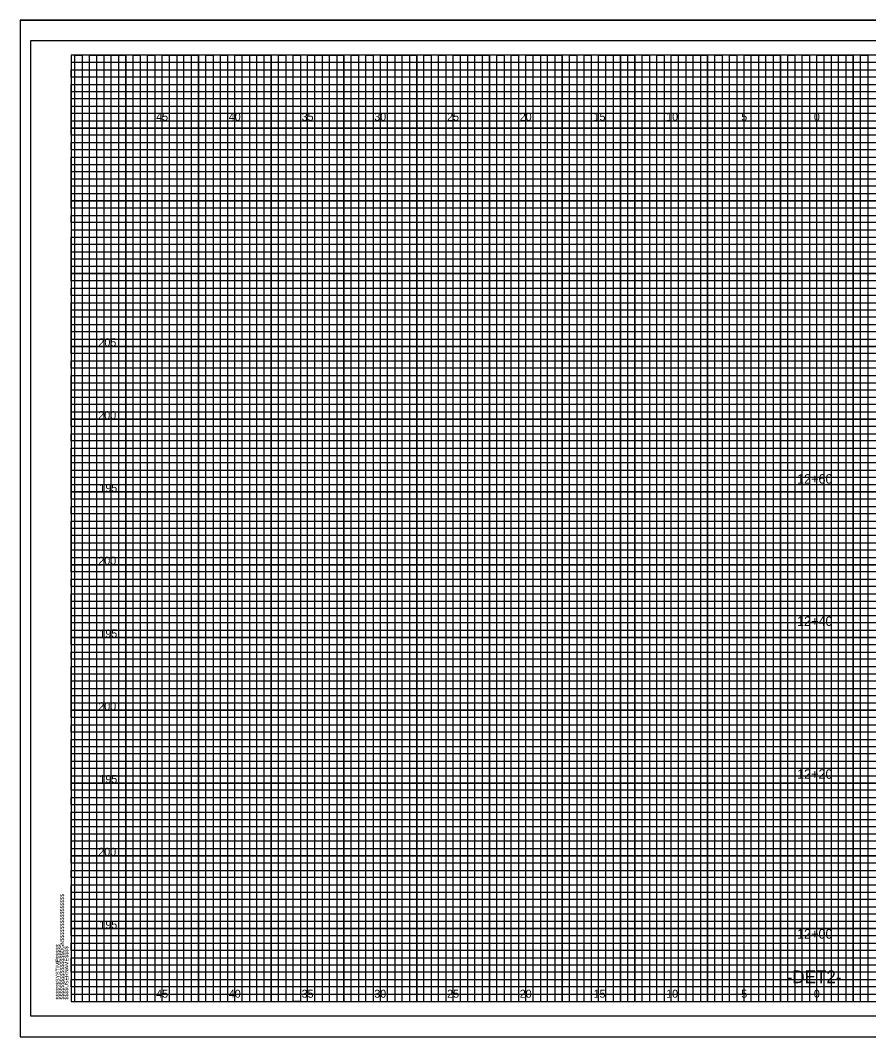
# Model space of a CAD drawing. Extents: x -4 to 103, y -2 to 209.
# Drawn here: x -3.5 to 54.8, y 139.2 to 209.1 of the extents above; entities that cross this region are included whole.
import ezdxf

# ---------------------------------------------------------------- set-up
doc = ezdxf.new("R2010")
doc.units = 0
for name, color, linetype in [('Exist XS Ground Line', 7, 'Continuous'), ('Old_Level_10', 7, 'Continuous'), ('Old_Level_3', 7, 'Continuous'), ('Old_Level_5', 7, 'Continuous'), ('Old_Level_8', 7, 'Continuous'), ('Prop XS Dump Level', 7, 'Continuous'), ('Prop XS Elevation Labels', 7, 'Continuous'), ('Prop XS EOT Tick Mark', 7, 'Continuous'), ('Prop XS Finish Grade', 7, 'Continuous'), ('Prop XS Hydro Elevations', 7, 'Continuous'), ('Prop XS Label Text', 7, 'Continuous')]:
    doc.layers.add(name, color=color, linetype=linetype)

msp = doc.modelspace()

# ---------------------------------------------------------------- linework, layer by layer
at = {"layer": 'Exist XS Ground Line'}
msp.add_lwpolyline([(103, 207.65), (-2.8, 207.65), (-2.8, 140.65), (103, 140.65)], close=True, dxfattribs=at)
at = {"layer": 'Old_Level_10'}
for p, q in [((1.25, 141.65), (1.25, 206.65)), ((3.75, 141.65), (3.75, 206.65)), ((6.25, 141.65), (6.25, 206.65)), ((8.75, 141.65), (8.75, 206.65)), ((11.25, 141.65), (11.25, 206.65)), ((13.75, 141.65), (13.75, 206.65)), ((16.25, 141.65), (16.25, 206.65)), ((18.75, 141.65), (18.75, 206.65)), ((21.25, 141.65), (21.25, 206.65)), ((23.75, 141.65), (23.75, 206.65)), ((26.25, 141.65), (26.25, 206.65)), ((28.75, 141.65), (28.75, 206.65)), ((31.25, 141.65), (31.25, 206.65)), ((33.75, 141.65), (33.75, 206.65)), ((36.25, 141.65), (36.25, 206.65)), ((38.75, 141.65), (38.75, 206.65)), ((41.25, 141.65), (41.25, 206.65)), ((43.75, 141.65), (43.75, 206.65)), ((46.25, 141.65), (46.25, 206.65)), ((48.75, 141.65), (48.75, 206.65)), ((51.25, 141.65), (51.25, 206.65)), ((53.75, 141.65), (53.75, 206.65)), ((0, 204.15), (74.25, 204.15)), ((0, 201.65), (102.5, 201.65)), ((0, 199.15), (102.5, 199.15)), ((0, 196.65), (102.5, 196.65)), ((0, 194.15), (102.5, 194.15)), ((0, 191.65), (102.5, 191.65)), ((0, 189.15), (102.5, 189.15)), ((0, 186.65), (102.5, 186.65)), ((0, 184.15), (102.5, 184.15)), ((0, 181.65), (102.5, 181.65)), ((0, 179.15), (102.5, 179.15)), ((0, 176.65), (102.5, 176.65)), ((0, 174.15), (102.5, 174.15)), ((0, 171.65), (102.5, 171.65)), ((0, 169.15), (102.5, 169.15)), ((0, 166.65), (102.5, 166.65)), ((0, 164.15), (102.5, 164.15)), ((0, 161.65), (102.5, 161.65)), ((0, 159.15), (102.5, 159.15)), ((0, 156.65), (102.5, 156.65)), ((0, 154.15), (102.5, 154.15)), ((0, 151.65), (102.5, 151.65)), ((0, 149.15), (102.5, 149.15)), ((0, 146.65), (102.5, 146.65)), ((0, 144.15), (102.5, 144.15))]:
    msp.add_line(p, q, dxfattribs=at)
at = {"layer": 'Old_Level_3'}
for p, q in [((-3.5, 209.05), (103.4, 209.05)), ((-3.5, 209.05), (-3.5, 139.225)), ((-3.5, 139.225), (103.4, 139.225))]:
    msp.add_line(p, q, dxfattribs=at)
at = {"layer": 'Old_Level_5'}
msp.add_lwpolyline([(103.4, 209.05), (-3.5, 209.05), (-3.5, 139.225), (103.4, 139.225)], close=True, dxfattribs=at)
at = {"layer": 'Old_Level_8'}
for points in [[(1.25, 141.65), (1.25, 206.65), (3.75, 206.65), (3.75, 141.65), (6.25, 141.65), (6.25, 206.65), (8.75, 206.65), (8.75, 141.65), (11.25, 141.65), (11.25, 206.65), (13.75, 206.65), (13.75, 141.65), (16.25, 141.65), (16.25, 206.65), (18.75, 206.65), (18.75, 141.65), (21.25, 141.65), (21.25, 206.65), (23.75, 206.65), (23.75, 141.65), (26.25, 141.65), (26.25, 206.65), (28.75, 206.65), (28.75, 141.65), (31.25, 141.65), (31.25, 206.65), (33.75, 206.65), (33.75, 141.65), (36.25, 141.65), (36.25, 206.65), (38.75, 206.65), (38.75, 141.65), (41.25, 141.65), (41.25, 206.65), (43.75, 206.65), (43.75, 141.65), (46.25, 141.65), (46.25, 206.65), (48.75, 206.65), (48.75, 141.65), (51.25, 141.65), (51.25, 206.65), (53.75, 206.65), (53.75, 141.65)], [(102.5, 201.65), (0, 201.65), (0, 204.15), (74.25, 204.15)], [(102.5, 196.65), (0, 196.65), (0, 199.15), (102.5, 199.15)], [(102.5, 191.65), (0, 191.65), (0, 194.15), (102.5, 194.15)], [(102.5, 186.65), (0, 186.65), (0, 189.15), (102.5, 189.15)], [(102.5, 181.65), (0, 181.65), (0, 184.15), (102.5, 184.15)], [(102.5, 176.65), (0, 176.65), (0, 179.15), (102.5, 179.15)], [(102.5, 171.65), (0, 171.65), (0, 174.15), (102.5, 174.15)], [(102.5, 166.65), (0, 166.65), (0, 169.15), (102.5, 169.15)], [(102.5, 161.65), (0, 161.65), (0, 164.15), (102.5, 164.15)], [(102.5, 156.65), (0, 156.65), (0, 159.15), (102.5, 159.15)], [(102.5, 151.65), (0, 151.65), (0, 154.15), (102.5, 154.15)], [(102.5, 146.65), (0, 146.65), (0, 149.15), (102.5, 149.15)], [(0, 144.15), (102.5, 144.15)]]:
    msp.add_lwpolyline(points, dxfattribs=at)
at = {"layer": 'Prop XS Dump Level'}
msp.add_lwpolyline([(102.5, 206.65), (0, 206.65), (0, 141.65), (102.5, 141.65)], close=True, dxfattribs=at)
at = {"layer": 'Prop XS Finish Grade'}
for points in [[(0, 203.65), (0, 204.65), (74.25, 204.65), (74.25, 205.15), (0, 205.15), (0, 205.65), (74.25, 205.65), (74.25, 206.15), (0, 206.15)], [(0.25, 141.65), (0.25, 206.65), (0.75, 206.65), (0.75, 141.65), (1.75, 141.65), (1.75, 206.65), (2.25, 206.65), (2.25, 141.65), (2.75, 141.65), (2.75, 206.65), (3.25, 206.65), (3.25, 141.65), (4.25, 141.65), (4.25, 206.65), (4.75, 206.65), (4.75, 141.65), (5.25, 141.65), (5.25, 206.65), (5.75, 206.65), (5.75, 141.65), (6.75, 141.65), (6.75, 206.65), (7.25, 206.65), (7.25, 141.65), (7.75, 141.65), (7.75, 206.65), (8.25, 206.65), (8.25, 141.65), (9.25, 141.65), (9.25, 206.65), (9.75, 206.65), (9.75, 141.65), (10.25, 141.65), (10.25, 206.65), (10.75, 206.65), (10.75, 141.65), (11.75, 141.65), (11.75, 206.65), (12.25, 206.65), (12.25, 141.65), (12.75, 141.65), (12.75, 206.65), (13.25, 206.65), (13.25, 141.65), (14.25, 141.65), (14.25, 206.65), (14.75, 206.65), (14.75, 141.65), (15.75, 141.65), (15.25, 141.65), (15.25, 206.65), (15.75, 206.65), (15.75, 141.65), (16.75, 141.65), (16.75, 206.65), (17.25, 206.65), (17.25, 141.65), (17.75, 141.65), (17.75, 206.65), (18.25, 206.65), (18.25, 141.65), (19.25, 141.65), (19.25, 206.65), (19.75, 206.65), (19.75, 141.65), (20.25, 141.65), (20.25, 206.65), (20.75, 206.65), (20.75, 141.65), (21.75, 141.65), (21.75, 206.65), (22.25, 206.65), (22.25, 141.65), (22.75, 141.65), (22.75, 206.65), (23.25, 206.65), (23.25, 141.65), (24.25, 141.65), (24.25, 206.65), (24.75, 206.65), (24.75, 141.65), (25.25, 141.65), (25.25, 206.65), (25.75, 206.65), (25.75, 141.65), (26.75, 141.65), (26.75, 206.65), (27.25, 206.65), (27.25, 141.65), (27.75, 141.65), (27.75, 206.65), (28.25, 206.65), (28.25, 141.65), (29.25, 141.65), (29.25, 206.65), (29.75, 206.65), (29.75, 141.65), (30.25, 141.65), (30.25, 206.65), (30.75, 206.65), (30.75, 141.65)], [(30.75, 141.65), (31.75, 141.65), (31.75, 206.65), (32.25, 206.65), (32.25, 141.65), (32.75, 141.65), (32.75, 206.65), (33.25, 206.65), (33.25, 141.65), (34.25, 141.65), (34.25, 206.65), (34.75, 206.65), (34.75, 141.65), (35.25, 141.65), (35.25, 206.65), (35.75, 206.65), (35.75, 141.65), (36.75, 141.65), (36.75, 206.65), (37.25, 206.65), (37.25, 141.65), (37.75, 141.65), (37.75, 206.65), (37.75, 141.65)], [(38.25, 206.65), (38.25, 141.65), (39.25, 141.65), (39.25, 206.65), (39.75, 206.65), (39.75, 141.65), (40.25, 141.65), (40.25, 206.65), (40.75, 206.65), (40.75, 141.65), (41.75, 141.65), (41.75, 206.65), (42.25, 206.65), (42.25, 141.65), (42.75, 141.65), (42.75, 206.65), (43.25, 206.65), (43.25, 141.65), (43.75, 141.65), (44.25, 141.65), (44.25, 206.65), (44.75, 206.65), (44.75, 141.65), (45.25, 141.65), (45.25, 206.65), (45.75, 206.65), (45.75, 141.65), (46.75, 141.65), (46.75, 206.65), (47.25, 206.65), (47.25, 141.65), (47.75, 141.65), (47.75, 206.65), (48.25, 206.65), (48.25, 141.65), (49.25, 141.65), (49.25, 206.65), (49.75, 206.65), (49.75, 141.65), (50.25, 141.65), (50.25, 206.65), (50.75, 206.65), (50.75, 141.65), (51.75, 141.65), (51.75, 206.65), (52.25, 206.65), (52.25, 141.65), (52.75, 141.65), (52.75, 206.65), (53.25, 206.65), (53.25, 141.65), (54.25, 141.65), (54.25, 206.65), (54.75, 206.65), (54.75, 141.65), (55.25, 141.65)], [(102.5, 203.65), (0, 203.65)], [(102.5, 202.65), (0, 202.65), (0, 203.15), (102.5, 203.15)], [(102.5, 201.15), (0, 201.15), (0, 202.15), (102.5, 202.15)], [(102.5, 200.15), (0, 200.15), (0, 200.65), (102.5, 200.65)], [(102.5, 198.65), (0, 198.65), (0, 199.65), (102.5, 199.65)], [(102.5, 197.65), (0, 197.65), (0, 198.15), (102.5, 198.15)], [(102.5, 196.15), (0, 196.15), (0, 197.15), (102.5, 197.15)], [(102.5, 195.15), (0, 195.15), (0, 195.65), (102.5, 195.65)], [(0, 194.65), (102.5, 194.65)], [(102.5, 193.65), (0, 193.65)], [(102.5, 192.65), (0, 192.65), (0, 193.15), (102.5, 193.15)], [(102.5, 191.15), (0, 191.15), (0, 192.15), (102.5, 192.15)], [(102.5, 190.15), (0, 190.15), (0, 190.65), (102.5, 190.65)], [(102.5, 188.65), (0, 188.65), (0, 189.65), (102.5, 189.65)], [(102.5, 187.65), (0, 187.65), (0, 188.15), (102.5, 188.15)], [(102.5, 186.15), (0, 186.15), (0, 187.15), (102.5, 187.15)], [(102.5, 185.15), (0, 185.15), (0, 185.65), (102.5, 185.65)], [(102.5, 183.65), (0, 183.65), (0, 184.65), (102.5, 184.65)], [(102.5, 182.65), (0, 182.65), (0, 183.15), (102.5, 183.15)], [(102.5, 181.15), (0, 181.15), (0, 182.15), (102.5, 182.15)], [(102.5, 180.15), (0, 180.15), (0, 180.65), (102.5, 180.65)], [(102.5, 178.65), (0, 178.65), (0, 179.65), (102.5, 179.65)], [(102.5, 177.65), (0, 177.65), (0, 178.15), (102.5, 178.15)], [(102.5, 176.15), (0, 176.15), (0, 177.15), (102.5, 177.15)], [(102.5, 175.15), (0, 175.15), (0, 175.65), (102.5, 175.65)], [(102.5, 173.65), (0, 173.65), (0, 174.65), (102.5, 174.65)], [(102.5, 172.65), (0, 172.65), (0, 173.15)], [(0, 173.15), (102.5, 173.15)], [(102.5, 171.15), (0, 171.15), (0, 172.15), (102.5, 172.15)], [(102.5, 170.15), (0, 170.15), (0, 170.65), (102.5, 170.65)], [(102.5, 168.65), (0, 168.65), (0, 169.65), (102.5, 169.65)], [(102.5, 167.65), (0, 167.65), (0, 168.15), (102.5, 168.15)], [(102.5, 166.15), (0, 166.15), (0, 167.15), (102.5, 167.15)], [(102.5, 165.15), (0, 165.15), (0, 165.65), (102.5, 165.65)], [(102.5, 163.65), (0, 163.65), (0, 164.65), (102.5, 164.65)], [(102.5, 162.65), (0, 162.65), (0, 163.15), (102.5, 163.15)], [(102.5, 161.15), (0, 161.15), (0, 162.15), (102.5, 162.15)], [(102.5, 160.15), (0, 160.15), (0, 160.65), (102.5, 160.65)], [(102.5, 158.65), (0, 158.65), (0, 159.65), (102.5, 159.65)], [(102.5, 157.65), (0, 157.65), (0, 158.15), (102.5, 158.15)], [(102.5, 156.15), (0, 156.15), (0, 157.15), (102.5, 157.15)], [(102.5, 155.15), (0, 155.15), (0, 155.65), (102.5, 155.65)], [(102.5, 153.65), (0, 153.65), (0, 154.65), (102.5, 154.65)], [(102.5, 152.65), (0, 152.65), (0, 153.15), (102.5, 153.15)], [(102.5, 151.15), (0, 151.15), (0, 152.15), (102.5, 152.15)], [(102.5, 150.15), (0, 150.15), (0, 150.65), (102.5, 150.65)], [(102.5, 148.65), (0, 148.65), (0, 149.65), (102.5, 149.65)], [(102.5, 147.65), (0, 147.65), (0, 148.15), (102.5, 148.15)], [(102.5, 146.15), (0, 146.15), (0, 147.15), (102.5, 147.15)], [(102.5, 145.15), (0, 145.15), (0, 145.65), (102.5, 145.65)], [(102.5, 143.65), (0, 143.65), (0, 144.65), (102.5, 144.65)], [(102.5, 142.65), (0, 142.65), (0, 143.15), (102.5, 143.15)], [(0, 142.15), (102.5, 142.15)]]:
    msp.add_lwpolyline(points, dxfattribs=at)

# ---------------------------------------------------------------- texts
at = {"layer": 'Old_Level_8'}
msp.add_text('040397', height=0.0025, rotation=90, dxfattribs=at).set_placement((-0.0007, 206.6364))
at = {"layer": 'Prop XS Dump Level'}
for s, p in [('$$$$$$$$$$$$$$$$DGN$$$$$$$$$$$$$$$$', (-0.5, 141.775)), ('$$$$$$SYSTIME$$$$$', (-0.7973, 141.7747)), ('$$$$USERNAME$$$$', (-0.2, 141.775))]:
    msp.add_text(s, height=0.2625, rotation=90, dxfattribs=at).set_placement(p)
at = {"layer": 'Prop XS Elevation Labels'}
for s, p in [('45', (5.8399, 202.15)), ('40', (10.8313, 202.15)), ('35', (15.8399, 202.15)), ('30', (20.8313, 202.15)), ('25', (25.8399, 202.15)), ('20', (30.8313, 202.15)), ('15', (35.9058, 202.15)), ('10', (40.8971, 202.15)), ('5', (46.0574, 202.15)), ('0', (51.0488, 202.15)), ('0', (51.0488, 202.15)), ('45', (5.8399, 141.9)), ('40', (10.8313, 141.9)), ('35', (15.8399, 141.9)), ('30', (20.8313, 141.9)), ('25', (25.8399, 141.9)), ('20', (30.8313, 141.9)), ('15', (35.9058, 141.9)), ('10', (40.8971, 141.9)), ('5', (46.0574, 141.9)), ('0', (51.0488, 141.9)), ('0', (51.0488, 141.9))]:
    msp.add_text(s, height=0.55, dxfattribs=at).set_placement(p)
at = {"layer": 'Prop XS EOT Tick Mark'}
msp.add_text('-DET2-', height=0.875, dxfattribs=at).set_placement((49.1786, 142.9))
at = {"layer": 'Prop XS Hydro Elevations'}
for s, p in [('12+60', (49.8934, 177.2185)), ('12+40', (49.8934, 167.4436)), ('12+20', (49.8934, 156.9412)), ('12+00', (49.8934, 145.9637))]:
    msp.add_text(s, height=0.65, dxfattribs=at).set_placement(p)
at = {"layer": 'Prop XS Label Text'}
for s, p in [('205', (1.8724, 186.65)), ('200', (1.8638, 181.65)), ('195', (1.9383, 176.65)), ('200', (1.8638, 171.65)), ('195', (1.9383, 166.65)), ('200', (1.8638, 161.65)), ('195', (1.9383, 156.65)), ('200', (1.8638, 151.65)), ('195', (1.9383, 146.65))]:
    msp.add_text(s, height=0.55, dxfattribs=at).set_placement(p)

doc.saveas('drawing.dxf')
